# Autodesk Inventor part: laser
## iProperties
Shininess: 64.0
Length Units: 11269
Angle Units: 11279
Time Units: 11290
Mass Units: 11283
Length Display Precision: 3
Angle Display Precision: 2
Compacted: True
Part Number: laser
Document SubType Name: Modeling
Created: 2004-07
Designer: Peter
Manufacturer: Standard
Standards Organization: Custom
Density: 0.0
Volumn: 0.0
Area: 0.0
PropertySet Name: Model Information
Control State: 0
Master: False
Checked Out: False
Author: Peter
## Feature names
1. Extrusion1
